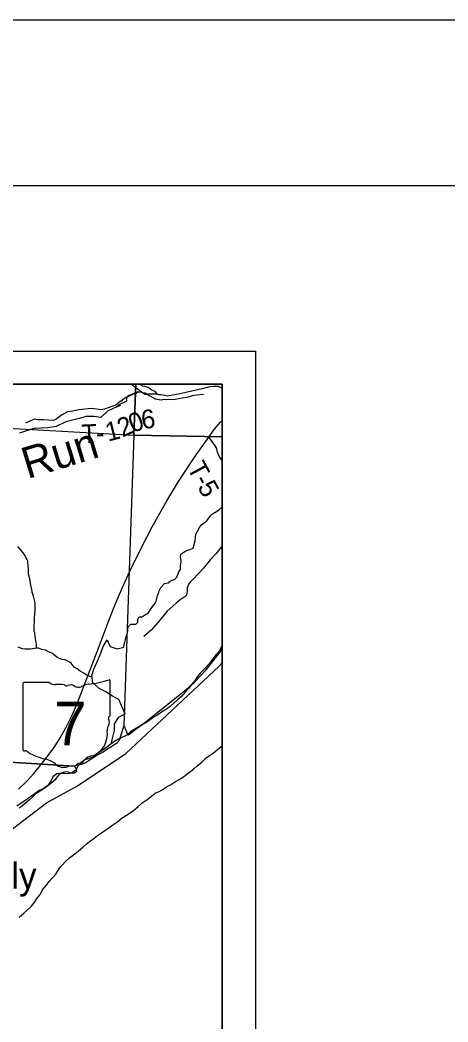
# Model space of a CAD drawing. Extents: x 6.3 to 40.3, y 9 to 31.
# Drawn here: x 14.633 to 15.927, y 28.019 to 31.046 of the extents above; entities that cross this region are included whole.
import ezdxf

# ---------------------------------------------------------------- set-up
doc = ezdxf.new("R2010")
doc.units = 0
for name, color, linetype in [('Default', 7, 'Continuous'), ('GM_X_Corporation', 7, 'Continuous'), ('GM_X_Major_River', 7, 'Continuous'), ('GM_X_Minor_River', 7, 'Continuous'), ('GM_X_Minor_River_Text', 7, 'Continuous'), ('GM_X_Section', 7, 'Continuous'), ('GM_X_State_Location', 7, 'Continuous'), ('GM_X_State_Route', 7, 'Continuous'), ('GM_X_State_Shield', 7, 'Continuous'), ('GM_X_Township_Road', 7, 'Continuous'), ('GM_X_Township_Road_Text', 7, 'Continuous'), ('GM_X_Unincorporated_Text', 7, 'Continuous'), ('SH_Border', 7, 'Continuous'), ('SH_Cut_Line', 7, 'Continuous'), ('SH_Data', 7, 'Continuous')]:
    doc.layers.add(name, color=color, linetype=linetype)

msp = doc.modelspace()

# ---------------------------------------------------------------- linework, layer by layer
at = {"layer": 'Default'}
for points in [[(13.8699, 27.9843), (13.9229, 28.0334), (14.1255, 28.1814), (14.1838, 28.2048), (14.2088, 28.2297), (14.3175, 28.3072), (14.3656, 28.3529), (14.5068, 28.5239), (14.7136, 28.6814), (14.8068, 28.7324), (14.9534, 28.8297), (15.2353, 29.0934), (15.2446, 29.1038), (15.2446, 29.9457), (12.9998, 29.9457), (12.9672, 29.1426), (12.9544, 28.3711), (12.9197, 27.4857)], [(15.2446, 27.6302), (15.2446, 29.9457), (13.1323, 29.9457), (13.13, 29.8856), (13.116, 29.2473), (13.1156, 29.231), (13.1136, 29.1637), (13.0974, 28.6191), (13.0625, 27.76)]]:
    msp.add_lwpolyline(points, dxfattribs=at)
at = {"layer": 'GM_X_Corporation'}
for points in [[(14.9834, 29.9457), (13.9997, 29.9457), (13.9983, 29.8461), (14.9774, 29.7913)], [(15.2446, 29.7867), (15.2446, 29.9457), (14.9834, 29.9457), (14.9774, 29.7913)], [(15.2446, 29.1443), (15.2446, 29.7867), (14.9774, 29.7913), (14.9465, 28.9149), (14.9583, 28.8882), (14.9608, 28.8863), (14.961, 28.8861), (14.9874, 28.9065), (15.0109, 28.9236), (15.135, 29.0228), (15.1604, 29.0456), (15.1954, 29.0826)]]:
    msp.add_lwpolyline(points, close=True, dxfattribs=at)
at = {"layer": 'GM_X_Major_River'}
for points in [[(15.2446, 29.1551), (15.2406, 29.1498), (15.2362, 29.1394), (15.2254, 29.1282), (15.2128, 29.1117), (15.204, 29.0998), (15.1924, 29.0878), (15.179, 29.0735), (15.1701, 29.0627), (15.1605, 29.0489), (15.1497, 29.0366), (15.1431, 29.027), (15.1316, 29.0138), (15.1223, 29.0034), (15.1092, 28.9918), (15.0992, 28.9825), (15.0872, 28.9717), (15.076, 28.9643), (15.061, 28.9549), (15.0494, 28.9471), (15.0389, 28.9408), (15.0262, 28.9319), (15.0131, 28.9229), (15.0018, 28.9163), (14.9921, 28.91), (14.9801, 28.903), (14.9681, 28.8967), (14.9561, 28.8855)], [(14.9561, 28.8855), (14.935, 28.8751), (14.923, 28.8689), (14.9132, 28.8623), (14.8997, 28.8522), (14.8881, 28.844), (14.8776, 28.8362), (14.8653, 28.8277), (14.8536, 28.8203), (14.8401, 28.8143), (14.8295, 28.8104), (14.8168, 28.8014), (14.8082, 28.7914), (14.802, 28.7792), (14.7889, 28.7706), (14.7768, 28.7689), (14.7669, 28.7698), (14.757, 28.7697), (14.7442, 28.7683), (14.7329, 28.7598), (14.7267, 28.7468), (14.7174, 28.7337), (14.7047, 28.7244), (14.6908, 28.7184), (14.6788, 28.7095), (14.6687, 28.7017), (14.6574, 28.6936), (14.6473, 28.6873), (14.6368, 28.68), (14.6237, 28.6706)], [(14.9763, 28.6577), (14.9894, 28.6693), (15.0028, 28.6806), (15.0167, 28.6899), (15.0309, 28.7008), (15.0421, 28.7097), (15.0533, 28.7153), (15.0631, 28.72), (15.0758, 28.7289), (15.0878, 28.7356), (15.1036, 28.745), (15.1145, 28.7513), (15.1276, 28.7595), (15.1384, 28.7684), (15.1481, 28.7758), (15.1586, 28.7839), (15.169, 28.7925), (15.1829, 28.8037), (15.1955, 28.8165), (15.2079, 28.8254), (15.2184, 28.8321), (15.2296, 28.8421), (15.2441, 28.853), (15.2446, 28.8534)], [(14.6306, 28.336), (14.6444, 28.348), (14.6545, 28.3569), (14.6676, 28.3689), (14.678, 28.382), (14.6847, 28.3927), (14.6951, 28.4054), (14.7013, 28.4177), (14.7128, 28.4323), (14.7203, 28.4423), (14.7411, 28.4654), (14.7511, 28.4815), (14.7615, 28.4935), (14.7697, 28.5031), (14.7828, 28.5143), (14.7947, 28.5236), (14.8086, 28.5349), (14.8228, 28.5469), (14.8329, 28.5558), (14.8426, 28.5628), (14.8572, 28.5737), (14.8673, 28.5822), (14.8793, 28.5903), (14.8898, 28.5977), (14.9026, 28.6067), (14.9172, 28.616), (14.9292, 28.6246), (14.9423, 28.6354), (14.9605, 28.647)], [(14.9605, 28.647), (14.9763, 28.6577)]]:
    msp.add_lwpolyline(points, dxfattribs=at)
at = {"layer": 'GM_X_Minor_River'}
for points in [[(15.188, 29.9146), (15.1763, 29.9132), (15.168, 29.9123), (15.1574, 29.9117), (15.1472, 29.9088), (15.1378, 29.9059), (15.1245, 29.9033), (15.1132, 29.9012), (15.1026, 29.8994), (15.089, 29.8984), (15.0825, 29.899), (15.0727, 29.898), (15.0666, 29.8994), (15.0594, 29.8973), (15.0423, 29.9), (15.0269, 29.9095), (15.0188, 29.9135), (15.0116, 29.9145), (15.0039, 29.92), (14.9686, 29.9457)], [(14.9228, 29.8755), (14.9332, 29.8838), (14.9562, 29.8953), (14.9562, 29.9068), (14.9906, 29.924), (14.9792, 29.9125)], [(14.9372, 29.8813), (14.9165, 29.873), (14.8972, 29.8643), (14.8777, 29.8447), (14.8561, 29.8481), (14.8323, 29.8477), (14.813, 29.8424), (14.7921, 29.8371), (14.7717, 29.8318), (14.7429, 29.8179), (14.7176, 29.8137), (14.6971, 29.8126), (14.6759, 29.8114), (14.6562, 29.8054), (14.6312, 29.7979)], [(14.9465, 29.1512), (14.9485, 29.1592), (14.9498, 29.1664), (14.9516, 29.1741), (14.9533, 29.1806), (14.9558, 29.1882), (14.9576, 29.1944), (14.9589, 29.2016), (14.9595, 29.2088), (14.9624, 29.215), (14.9684, 29.2204), (14.9752, 29.2202), (14.9832, 29.2208), (14.9891, 29.2262), (14.9897, 29.2346), (14.9937, 29.2431), (15.0009, 29.2432), (15.0144, 29.2504), (15.0204, 29.2539), (15.0318, 29.2705), (15.0421, 29.2837), (15.0443, 29.2902), (15.0471, 29.2986), (15.0492, 29.307), (15.0514, 29.3135), (15.0535, 29.3212), (15.0593, 29.3316), (15.0704, 29.3432), (15.081, 29.3457), (15.0877, 29.3512), (15.0937, 29.3536), (15.1016, 29.3565), (15.1068, 29.3627), (15.1137, 29.3788), (15.1181, 29.3861), (15.1182, 29.3964), (15.1192, 29.4025), (15.1206, 29.4086), (15.1189, 29.418), (15.118, 29.4252), (15.1197, 29.4321), (15.1317, 29.4404), (15.1377, 29.4435), (15.1467, 29.4464), (15.1561, 29.4504), (15.1621, 29.4722), (15.1637, 29.4848), (15.1651, 29.4928), (15.1694, 29.5016), (15.1767, 29.5151), (15.183, 29.5221), (15.1976, 29.5327), (15.2079, 29.5473), (15.215, 29.5539), (15.2269, 29.561), (15.2337, 29.5661), (15.2441, 29.5755), (15.2446, 29.5759)], [(14.6835, 29.148), (14.6828, 29.1589), (14.6819, 29.1657), (14.6802, 29.1771), (14.6793, 29.1824), (14.6783, 29.1942), (14.6762, 29.1998), (14.6761, 29.2063), (14.6756, 29.2112), (14.6755, 29.2169), (14.6771, 29.2283), (14.6773, 29.2359), (14.6785, 29.2542), (14.6787, 29.2626), (14.6795, 29.2774), (14.6789, 29.285), (14.6781, 29.2895), (14.6735, 29.3054), (14.6695, 29.3171), (14.6685, 29.3258), (14.6644, 29.3436), (14.6638, 29.3512), (14.6605, 29.3652), (14.6584, 29.3712), (14.6584, 29.3894), (14.6575, 29.3951), (14.6564, 29.411), (14.6544, 29.4152), (14.6457, 29.4321), (14.6387, 29.4407), (14.627, 29.4548)], [(14.8508, 29.0622), (14.8459, 29.0619), (14.8336, 29.068), (14.8259, 29.0724), (14.8155, 29.0787), (14.8059, 29.086), (14.797, 29.0912), (14.788, 29.1027), (14.7834, 29.1057), (14.7742, 29.1108), (14.7696, 29.113), (14.7608, 29.1143), (14.7513, 29.1167), (14.7448, 29.1208), (14.7382, 29.126), (14.7293, 29.1326), (14.7213, 29.1358), (14.7105, 29.1417), (14.6987, 29.1444), (14.6895, 29.1484), (14.6827, 29.1479), (14.677, 29.147), (14.6653, 29.1452), (14.6592, 29.1455), (14.6482, 29.1452), (14.6406, 29.1462), (14.6276, 29.1508)], [(14.9507, 28.9495), (14.9322, 28.9933), (14.9125, 29.0032), (14.8925, 29.016), (14.8727, 29.0266), (14.8534, 29.0432), (14.8504, 29.0655), (14.8561, 29.0851), (14.8693, 29.1138), (14.8773, 29.1334), (14.8848, 29.1531), (14.8963, 29.1738), (14.906, 29.1527), (14.9272, 29.1459), (14.9465, 29.1512)], [(14.9086, 28.8588), (14.9191, 28.8997), (14.9187, 28.9193), (14.9314, 28.9393), (14.9507, 28.9495), (14.9503, 28.9495)]]:
    msp.add_lwpolyline(points, dxfattribs=at)
at = {"layer": 'GM_X_Section'}
msp.add_lwpolyline([(13.9983, 29.8461), (14.9774, 29.7913), (14.9465, 28.9149), (14.9325, 28.8696), (14.9246, 28.8604), (14.9108, 28.8511), (14.8984, 28.8437), (14.892, 28.8386), (14.8845, 28.8344), (14.8687, 28.8258), (14.8481, 28.8126), (14.8335, 28.8028), (14.8222, 28.7974), (14.7965, 28.7913), (13.9707, 28.8429)], close=True, dxfattribs=at)
msp.add_lwpolyline([(13.9707, 28.8429), (14.7965, 28.7913), (14.8031, 28.7834), (14.8028, 28.7747), (14.7976, 28.7708), (14.7931, 28.7696), (14.7889, 28.7703), (14.7836, 28.7714), (14.7786, 28.7739), (14.771, 28.7742), (14.7638, 28.7729), (14.7571, 28.7702), (14.7507, 28.7652), (14.7451, 28.7598), (14.7425, 28.7555), (14.7392, 28.7506), (14.7317, 28.7429), (14.7164, 28.7313), (14.7029, 28.7223), (14.6886, 28.7134), (14.6804, 28.7076), (14.6722, 28.6987), (14.661, 28.6887), (14.643, 28.674), (14.637, 28.669), (14.6303, 28.6643)], dxfattribs=at)
at = {"layer": 'GM_X_State_Route'}
msp.add_line((14.6829, 28.7792), (14.7014, 28.802), dxfattribs=at)
for points in [[(15.2036, 29.7859), (15.2197, 29.8083), (15.2392, 29.8306), (15.2446, 29.836)], [(14.7014, 28.802), (14.7147, 28.8185), (14.736, 28.8482), (14.7548, 28.8776), (14.773, 28.9094), (14.792, 28.9481), (14.8073, 28.983), (14.8738, 29.1563), (14.9015, 29.2313), (14.9213, 29.28), (14.9422, 29.3295), (14.9655, 29.381), (15.0006, 29.452), (15.033, 29.5142), (15.0769, 29.5935), (15.1124, 29.6519), (15.1656, 29.7327), (15.2036, 29.7859)], [(14.6286, 28.7226), (14.6536, 28.7461), (14.6753, 28.7698), (14.6829, 28.7792)]]:
    msp.add_lwpolyline(points, dxfattribs=at)
at = {"layer": 'GM_X_State_Shield'}
for p, q in [((14.6419, 29.0411), (14.6419, 28.841)), ((14.7217, 29.0445), (14.6445, 29.0445)), ((14.9056, 28.9448), (14.9056, 29.0495)), ((14.9056, 28.9448), (14.9056, 28.9448))]:
    msp.add_line(p, q, dxfattribs=at)
for centre, radius, start, end in [((14.6449, 29.0415), 0.00305, 98.1301, 188.1301), ((14.7401, 29.0678), 0.0296, 231.6195, 271.1119), ((14.7499, 28.9322), 0.1064, 80.4867, 94.9883), ((14.7741, 29.0426), 0.00855, 219.7921, 297.1024), ((14.7866, 29.0194), 0.0178, 54.4667, 119.1411), ((14.8096, 29.0512), 0.0214, 233.8562, 294.8282), ((14.8473, 28.9834), 0.0563, 97.3462, 120.7689), ((14.8117, 29.3174), 0.2796, 275.8445, 288.9065), ((14.9027, 29.0499), 0.00294, 351.8621, 97.738), ((14.9049, 28.9371), 0.00454, 107.944, 210.337), ((14.9025, 28.9444), 0.00314, 289.6038, 7.7341), ((14.9161, 28.901), 0.0198, 136.8065, 186.9296), ((14.876, 28.9239), 0.0273, 340.033, 23.6496), ((14.8273, 28.8877), 0.0699, 292.3089, 8.9858), ((14.645, 28.8405), 0.00308, 171.9584, 258.3066), ((14.6454, 28.861), 0.0235, 267.339, 280.6039), ((14.6502, 28.8294), 0.00848, 29.7484, 93.2717), ((14.7573, 29.0092), 0.2019, 240.4129, 257.1985), ((14.8568, 28.7848), 0.0383, 94.4031, 142.5768), ((14.6971, 28.7511), 0.0632, 47.1842, 75.836), ((14.7654, 28.8284), 0.0401, 230.7004, 286.2918), ((14.7886, 28.7592), 0.0329, 85.6951, 111.2099), ((14.7915, 28.8134), 0.0214, 268.777, 315.5493), ((14.8108, 28.7941), 0.00601, 65.7517, 132.6484), ((14.8083, 28.8216), 0.0226, 282.8732, 323.2771)]:
    msp.add_arc(centre, radius, start, end, dxfattribs=at)
at = {"layer": 'GM_X_Township_Road'}
for points in [[(15.2446, 29.9326), (15.2441, 29.9329), (15.2396, 29.9359), (15.2336, 29.9389), (15.2276, 29.9389), (15.2178, 29.9385), (15.2065, 29.9374), (15.184, 29.9313), (15.1433, 29.9223), (15.1163, 29.9163), (15.0997, 29.9133), (15.0794, 29.9099), (15.0711, 29.9118), (15.0591, 29.9133), (15.0531, 29.9133), (15.0486, 29.9156), (15.0419, 29.9234), (15.0313, 29.9279), (15.0208, 29.9355), (15.0118, 29.9385), (15.0042, 29.94), (14.9952, 29.9445), (14.9936, 29.9457)], [(15.0486, 29.9156), (15.02, 29.9156), (15.011, 29.9186), (15.0005, 29.9201), (14.9944, 29.9216), (14.9884, 29.9216), (14.9839, 29.9201), (14.9794, 29.9186), (14.9704, 29.914), (14.9629, 29.9111), (14.9538, 29.905), (14.9463, 29.9005), (14.9418, 29.8975), (14.9403, 29.8945), (14.9373, 29.8945), (14.9228, 29.8819), (14.9108, 29.8779), (14.8887, 29.8699), (14.8767, 29.8679), (14.8646, 29.8699), (14.8486, 29.8719), (14.8105, 29.8679), (14.7924, 29.8638), (14.7763, 29.8618), (14.7583, 29.8518), (14.7422, 29.8397), (14.7342, 29.8357), (14.7041, 29.8377), (14.688, 29.8377), (14.676, 29.8397), (14.6499, 29.8277)], [(15.2036, 29.7859), (15.2197, 29.8083), (15.2392, 29.8306), (15.2446, 29.836)], [(15.2446, 29.7152), (15.2347, 29.7281), (15.2305, 29.74), (15.227, 29.7532), (15.214, 29.7724), (15.2036, 29.7859)], [(15.2446, 29.4569), (15.2261, 29.4345), (15.2079, 29.4151), (15.1873, 29.3896), (15.1728, 29.3739), (15.1558, 29.3557), (15.1473, 29.3472), (15.1437, 29.3423), (15.1388, 29.3302), (15.1388, 29.3217), (15.1376, 29.3132), (15.1351, 29.3059), (15.117, 29.2938), (15.1048, 29.2841), (15.0781, 29.2598), (15.0563, 29.2331), (15.0308, 29.204), (15.0078, 29.1833)]]:
    msp.add_lwpolyline(points, dxfattribs=at)
at = {"layer": 'SH_Border'}
msp.add_lwpolyline([(7.8446, 30.5457), (39.8446, 30.5457), (39.8446, 9.5457), (7.8446, 9.5457)], close=True, dxfattribs=at)
at = {"layer": 'SH_Cut_Line'}
msp.add_lwpolyline([(6.3446, 9.0457), (40.3446, 9.0457), (40.3446, 31.0457), (6.3446, 31.0457)], close=True, dxfattribs=at)
msp.add_lwpolyline([(13.8699, 27.9843), (13.9229, 28.0334), (14.1255, 28.1814), (14.1838, 28.2048), (14.2088, 28.2297), (14.3175, 28.3072), (14.3656, 28.3529), (14.5068, 28.5239), (14.7136, 28.6814), (14.8068, 28.7324), (14.9534, 28.8297), (15.2353, 29.0934), (15.2446, 29.1038), (15.2446, 29.9457), (8.4446, 29.9457)], dxfattribs=at)
at = {"layer": 'SH_Data'}
for p, q in [((8.3446, 30.0457), (15.3446, 30.0457)), ((15.3446, 30.0457), (15.3446, 23.0457)), ((8.4446, 29.9457), (15.2446, 29.9457)), ((15.2446, 29.9457), (15.2446, 23.1457))]:
    msp.add_line(p, q, dxfattribs=at)

# ---------------------------------------------------------------- texts
at = {"layer": 'GM_X_Minor_River_Text'}
msp.add_text('Run', height=0.0947, rotation=17.057, dxfattribs=at).set_placement((14.6557, 29.6587))
at = {"layer": 'GM_X_State_Location'}
msp.add_text('7', height=0.000189, rotation=0, dxfattribs=at).set_placement((14.7423, 28.914))
for s in ['s', 'r']:
    msp.add_text(s, height=0.000189, dxfattribs=at).set_placement((14.7708, 28.9277))
at = {"layer": 'GM_X_State_Shield'}
msp.add_text('7', height=0.1318, dxfattribs=at).set_placement((14.736, 28.8551))
at = {"layer": 'GM_X_Township_Road_Text'}
for s, rotation, p in [('2', 23.9312, (14.9426, 29.7841)), ('0', 20.8539, (14.9739, 29.798)), ('6', 7.5465, (15.0032, 29.8096)), ('T', 2.4564, (14.8205, 29.7668)), ('1', 14.5709, (14.8992, 29.7719)), ('-', 3.3611, (14.864, 29.7687)), ('T', 298.2452, (15.137, 29.6937)), ('-', 298.2932, (15.1572, 29.6562)), ('5', 298.4767, (15.1683, 29.6355))]:
    msp.add_text(s, height=0.0568, rotation=rotation, dxfattribs=at).set_placement(p)
at = {"layer": 'GM_X_Unincorporated_Text'}
msp.add_text('Fly', height=0.07898, rotation=0, dxfattribs=at).set_placement((14.5423, 28.4211))

doc.saveas('drawing.dxf')
